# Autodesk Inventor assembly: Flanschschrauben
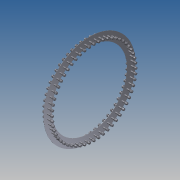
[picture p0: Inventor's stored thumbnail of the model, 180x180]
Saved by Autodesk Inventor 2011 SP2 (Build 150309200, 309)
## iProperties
Created: 2012-06
Part Number: Flanschschrauben
Document SubType Name: Assembly
Designer: JRE
Author: JRE
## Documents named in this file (4)
- E:\Users\jre\Documents\Inventor\Test\Flanschschrauben.iam
- E:\Users\jre\Documents\Inventor\Test\Schraub_Gruppe.iam
- E:\Users\jre\Documents\Inventor\Test\Schraub_Gruppe2.iam
- E:\Users\jre\Documents\Inventor\Test\Dichtung_56_1000.ipt
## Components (113 placed, 3 different names)
1. Dichtung_56_1000:1 — Passend:3, Passend:4, Passend:5
2. Schraub_Gruppe:1 [sub-assembly] — Radius_der_Anordnung, Passend:2
3. Schraub_Gruppe2:1 [sub-assembly] — Passend:2
4. Schraub_Gruppe:2 [sub-assembly]
5. Schraub_Gruppe2:2 [sub-assembly]
6. Schraub_Gruppe:3 [sub-assembly]
7. Schraub_Gruppe2:3 [sub-assembly]
8. Schraub_Gruppe:4 [sub-assembly]
9. Schraub_Gruppe2:4 [sub-assembly]
10. Schraub_Gruppe:5 [sub-assembly]
11. Schraub_Gruppe2:5 [sub-assembly]
12. Schraub_Gruppe:6 [sub-assembly]
13. Schraub_Gruppe2:6 [sub-assembly]
14. Schraub_Gruppe:7 [sub-assembly]
15. Schraub_Gruppe2:7 [sub-assembly]
16. Schraub_Gruppe:8 [sub-assembly]
17. Schraub_Gruppe2:8 [sub-assembly]
18. Schraub_Gruppe:9 [sub-assembly]
19. Schraub_Gruppe2:9 [sub-assembly]
20. Schraub_Gruppe:10 [sub-assembly]
21. Schraub_Gruppe2:10 [sub-assembly]
22. Schraub_Gruppe:11 [sub-assembly]
23. Schraub_Gruppe2:11 [sub-assembly]
24. Schraub_Gruppe:12 [sub-assembly]
25. Schraub_Gruppe2:12 [sub-assembly]
26. Schraub_Gruppe:13 [sub-assembly]
27. Schraub_Gruppe2:13 [sub-assembly]
28. Schraub_Gruppe:14 [sub-assembly]
29. Schraub_Gruppe2:14 [sub-assembly]
30. Schraub_Gruppe:15 [sub-assembly]
31. Schraub_Gruppe2:15 [sub-assembly]
32. Schraub_Gruppe:16 [sub-assembly]
33. Schraub_Gruppe2:16 [sub-assembly]
34. Schraub_Gruppe:17 [sub-assembly]
35. Schraub_Gruppe2:17 [sub-assembly]
36. Schraub_Gruppe:18 [sub-assembly]
37. Schraub_Gruppe2:18 [sub-assembly]
38. Schraub_Gruppe:19 [sub-assembly]
39. Schraub_Gruppe2:19 [sub-assembly]
40. Schraub_Gruppe:20 [sub-assembly]
41. Schraub_Gruppe2:20 [sub-assembly]
42. Schraub_Gruppe:21 [sub-assembly]
43. Schraub_Gruppe2:21 [sub-assembly]
44. Schraub_Gruppe:22 [sub-assembly]
45. Schraub_Gruppe2:22 [sub-assembly]
46. Schraub_Gruppe:23 [sub-assembly]
47. Schraub_Gruppe2:23 [sub-assembly]
48. Schraub_Gruppe:24 [sub-assembly]
49. Schraub_Gruppe2:24 [sub-assembly]
50. Schraub_Gruppe:25 [sub-assembly]
51. Schraub_Gruppe2:25 [sub-assembly]
52. Schraub_Gruppe:26 [sub-assembly]
53. Schraub_Gruppe2:26 [sub-assembly]
54. Schraub_Gruppe:27 [sub-assembly]
55. Schraub_Gruppe2:27 [sub-assembly]
56. Schraub_Gruppe:28 [sub-assembly]
57. Schraub_Gruppe2:28 [sub-assembly]
58. Schraub_Gruppe:29 [sub-assembly]
59. Schraub_Gruppe2:29 [sub-assembly]
60. Schraub_Gruppe:30 [sub-assembly]
61. Schraub_Gruppe2:30 [sub-assembly]
62. Schraub_Gruppe:31 [sub-assembly]
63. Schraub_Gruppe2:31 [sub-assembly]
64. Schraub_Gruppe:32 [sub-assembly]
65. Schraub_Gruppe2:32 [sub-assembly]
66. Schraub_Gruppe:33 [sub-assembly]
67. Schraub_Gruppe2:33 [sub-assembly]
68. Schraub_Gruppe:34 [sub-assembly]
69. Schraub_Gruppe2:34 [sub-assembly]
70. Schraub_Gruppe:35 [sub-assembly]
71. Schraub_Gruppe2:35 [sub-assembly]
72. Schraub_Gruppe:36 [sub-assembly]
73. Schraub_Gruppe2:36 [sub-assembly]
74. Schraub_Gruppe:37 [sub-assembly]
75. Schraub_Gruppe2:37 [sub-assembly]
76. Schraub_Gruppe:38 [sub-assembly]
77. Schraub_Gruppe2:38 [sub-assembly]
78. Schraub_Gruppe:39 [sub-assembly]
79. Schraub_Gruppe2:39 [sub-assembly]
80. Schraub_Gruppe:40 [sub-assembly]
81. Schraub_Gruppe2:40 [sub-assembly]
82. Schraub_Gruppe:41 [sub-assembly]
83. Schraub_Gruppe2:41 [sub-assembly]
84. Schraub_Gruppe:42 [sub-assembly]
85. Schraub_Gruppe2:42 [sub-assembly]
86. Schraub_Gruppe:43 [sub-assembly]
87. Schraub_Gruppe2:43 [sub-assembly]
88. Schraub_Gruppe:44 [sub-assembly]
89. Schraub_Gruppe2:44 [sub-assembly]
90. Schraub_Gruppe:45 [sub-assembly]
91. Schraub_Gruppe2:45 [sub-assembly]
92. Schraub_Gruppe:46 [sub-assembly]
93. Schraub_Gruppe2:46 [sub-assembly]
94. Schraub_Gruppe:47 [sub-assembly]
95. Schraub_Gruppe2:47 [sub-assembly]
96. Schraub_Gruppe:48 [sub-assembly]
97. Schraub_Gruppe2:48 [sub-assembly]
98. Schraub_Gruppe:49 [sub-assembly]
99. Schraub_Gruppe2:49 [sub-assembly]
100. Schraub_Gruppe:50 [sub-assembly]
101. Schraub_Gruppe2:50 [sub-assembly]
102. Schraub_Gruppe:51 [sub-assembly]
103. Schraub_Gruppe2:51 [sub-assembly]
104. Schraub_Gruppe:52 [sub-assembly]
105. Schraub_Gruppe2:52 [sub-assembly]
106. Schraub_Gruppe:53 [sub-assembly]
107. Schraub_Gruppe2:53 [sub-assembly]
108. Schraub_Gruppe:54 [sub-assembly]
109. Schraub_Gruppe2:54 [sub-assembly]
110. Schraub_Gruppe:55 [sub-assembly] — Passend:4, Passend:5
111. Schraub_Gruppe2:55 [sub-assembly]
112. Schraub_Gruppe:56 [sub-assembly]
113. Schraub_Gruppe2:56 [sub-assembly]
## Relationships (5: Mate 5)
- Radius_der_Anordnung [Mate]: Schraub_Gruppe:1
- Passend:2 [Mate]: Schraub_Gruppe:1 ↔ Schraub_Gruppe2:1
- Passend:3 [Mate]: Dichtung_56_1000:1
- Passend:4 [Mate]: Dichtung_56_1000:1 ↔ Schraub_Gruppe:55
- Passend:5 [Mate]: Dichtung_56_1000:1 ↔ Schraub_Gruppe:55
